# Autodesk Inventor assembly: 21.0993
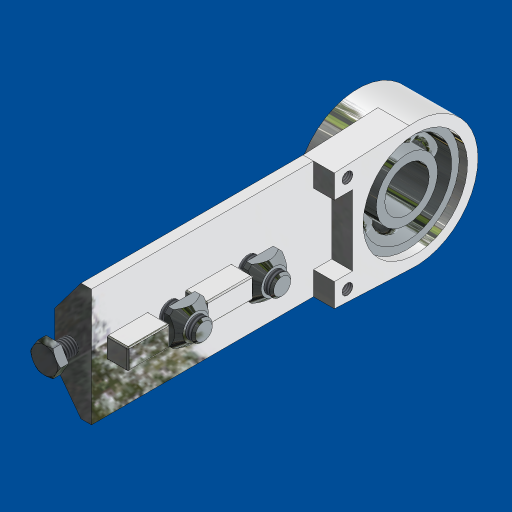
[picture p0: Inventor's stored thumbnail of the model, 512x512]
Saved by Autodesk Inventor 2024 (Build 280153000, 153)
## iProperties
Created: 2007-04
Part Number: 21.0993
Document SubType Name: Assembly
Designer: Andy Moles
Description: CONVEYOR BEARING 45
Author: Andy Moles
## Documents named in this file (6)
- L:\INVENTOR LIBRARIES\PARTS LIBRARY\BELT AND ROLLER CONVEYORS\21.0993 CONVEYOR BEARING 45.iam
- L:\INVENTOR LIBRARIES\PARTS LIBRARY\BELT AND ROLLER CONVEYORS\SUBCOMPONENTS\21.0993 CONVEYOR BEARING 45 M6X25.ipt
- L:\INVENTOR LIBRARIES\PARTS LIBRARY\FASTENING ELEMENTS\SCREWS CAP\21.1200 M8X16.ipt
- L:\INVENTOR LIBRARIES\PARTS LIBRARY\FASTENING ELEMENTS\NUTS\21.1351 M8 SQUARE NUT.ipt
- L:\INVENTOR LIBRARIES\PARTS LIBRARY\BELT AND ROLLER CONVEYORS\SUBCOMPONENTS\21.0993 15mm GRAY END CAP SHORT.ipt
- L:\INVENTOR LIBRARIES\PARTS LIBRARY\BELT AND ROLLER CONVEYORS\SUBCOMPONENTS\21.0993 CONVEYOR BEARING 45.ipt
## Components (8 placed, 5 different names)
1. 21.0993 CONVEYOR BEARING 45:1 — Flush:1, Mate:1, Flush:2, Insert:1, Insert:2, Insert:3, Insert:4, Insert:5, Insert:6, Insert:7
2. 21.0993 CONVEYOR BEARING 45 M6X25:1 — Insert:1
3. 21.1200 M8 x 16:1 — Insert:2
4. 21.1200 M8 x 16:2 — Insert:3
5. 21.1351 M8 SQUARE NUT:1 — Insert:4
6. 21.1351 M8 SQUARE NUT:2 — Insert:5
7. 21.0993 15mm GRAY END CAP SHORT:1 — Insert:6
8. 21.0993 15mm GRAY END CAP SHORT:2 — Insert:7
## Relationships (10: Insert 7, Flush 2, Mate 1)
- Flush:1: 21.0993 CONVEYOR BEARING 45:1
- Mate:1: 21.0993 CONVEYOR BEARING 45:1
- Flush:2: 21.0993 CONVEYOR BEARING 45:1
- Insert:1: 21.0993 CONVEYOR BEARING 45:1 ↔ 21.0993 CONVEYOR BEARING 45 M6X25:1
- Insert:2: 21.0993 CONVEYOR BEARING 45:1 ↔ 21.1200 M8 x 16:1
- Insert:3: 21.0993 CONVEYOR BEARING 45:1 ↔ 21.1200 M8 x 16:2
- Insert:4: 21.0993 CONVEYOR BEARING 45:1 ↔ 21.1351 M8 SQUARE NUT:1
- Insert:5: 21.0993 CONVEYOR BEARING 45:1 ↔ 21.1351 M8 SQUARE NUT:2
- Insert:6: 21.0993 CONVEYOR BEARING 45:1 ↔ 21.0993 15mm GRAY END CAP SHORT:1
- Insert:7: 21.0993 CONVEYOR BEARING 45:1 ↔ 21.0993 15mm GRAY END CAP SHORT:2
